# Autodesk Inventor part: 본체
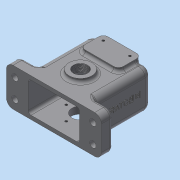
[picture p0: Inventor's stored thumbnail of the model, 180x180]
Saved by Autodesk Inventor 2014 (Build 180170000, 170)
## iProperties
Created: 2023-12
Part Number: 본체
Material: 일반
Document SubType Name: Modeling
Designer: dg
Density: 1 g/cm^3
Appearance: 기본값
Author: dg
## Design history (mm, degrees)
sketch "스케치1"
  geometry: L1 (50, -20)-(-50, -20); L2 (-50, -20)-(-50, 20); L3 (-50, 20)-(50, 20); L4 (50, 20)-(50, -20); L5 (31, -20)-(31, 20); L6 (-31, -20)-(-31, 20); 3 further points
  constraints: 12 end point, 4 point on line, 3 parallel, 2 midpoint, 2 perpendicular, 1 horizontal, 1 horizontal alignment, 1 vertical alignment
  dimensions: "d0" = 100 distance of L1.start L1.end; "d1" = 40 distance of L3.end L1.start; "d4" = 62 distance between parallel lines of L6 L5; "d5" = 31 distance from line of point (0, 0) L5
extrude "돌출1" new body sketch "스케치1" distance "d2" = 12; taper "d3" = 0 deg
extrude "돌출2" join sketch "스케치1" distance "d6" = 60; taper "d7" = 0 deg
sketch "스케치2"
  geometry: L1 (19, 72)-(81, 72) reference; L2 (30, 72)-(70, 72); L3 (70, 72)-(70, 48); L4 (70, 48)-(30, 48); L5 (30, 48)-(30, 72); L6 (100, 0)-(0, 0) reference; C1 r 12 at (50, 28); 2 further points
  constraints: 8 end point, 2 parallel, 2 vertical alignment, 1 centre point, 1 horizontal, 1 midpoint, 1 perpendicular, 1 point on line
  dimensions: "d8" = 24 distance between parallel lines of L4 L2; "d9" = 40 distance between parallel lines of L3 L5; "d12" = 24 diameter of C1; "d13" = 28 distance from line of C1.centre L6
extrude "돌출4" join sketch "스케치2" distance "d14" = 4; taper "d15" = 0 deg
sketch "스케치3"
  geometry: L1 (100, 0)-(0, 0) reference; C1 r 20 at (50, 28); 1 further point
  constraints: 1 centre point, 1 vertical alignment
  dimensions: "d16" = 40 diameter of C1; "d17" = 28 distance from line of L1 C1.centre
extrude "돌출5" join sketch "스케치3" distance "d18" = 4; taper "d19" = 0 deg
sketch "스케치5"
  geometry: L1 (-50, -20)-(50, -20) reference; L2 (50, 20)-(-50, 20) reference; L3 (-31, 20)-(-31, -20) reference; L4 (31, -20)-(31, 20) reference; L5 (-27, 16)-(27, 16); L6 (27, 16)-(27, -16); L7 (27, -16)-(-27, -16); L8 (-27, -16)-(-27, 16); 1 further point
  constraints: 8 end point, 2 parallel, 1 horizontal, 1 perpendicular
  dimensions: "d27" = 4 distance between parallel lines of L3 L8; "d28" = 4 distance between parallel lines of L4 L6; "d29" = 4 distance between parallel lines of L2 L5; "d30" = 4 distance between parallel lines of L1 L7
extrude "돌출7" cut sketch "스케치5" distance "d31" = 68; taper "d32" = 0 deg
sketch "스케치6"
  geometry: L1 (-20, 44)-(-20, 20) reference; L2 (-20, 20)-(20, 20) reference; L3 (20, 20)-(20, 44) reference; L4 (20, 44)-(-20, 44) reference; C1 r 12 at (0, 0) reference; 2 further points
  constraints: 1 coincident
hole "구멍1" sketch "스케치6" at (0, 0) diameter "d33" = 14.917; stored, may be unused: countersink angle "d37" = 90 deg, drill point angle "d39" = 0 deg; dims "d34" = 6, "d35" = 4, "d36" = 2, "d38" = 8
sketch "스케치7"
  geometry: C1 r 20 at (0, 0) reference; A1 r 15 centre (0, 0) between (0, 15) and (0, -15); 3 further points
  constraints: 4 point on circle, 2 horizontal alignment, 2 vertical alignment, 1 centre point, 1 coincident
  dimensions: "d40" = 30 diameter of A1
hole "구멍2" sketch "스케치7" at (0, 15), (0, -15), (-15, 0), (15, 0) diameter "d41" = 2.459; stored, may be unused: countersink angle "d45" = 90 deg, drill point angle "d47" = 0 deg; dims "d42" = 6, "d43" = 4, "d44" = 2, "d46" = 8
sketch "스케치8"
  geometry: C1 r 20 at (0, 0) reference; 2 further points
  constraints: 1 coincident
hole "구멍3" sketch "스케치8" at (0, 0) diameter "d48" = 18; stored, may be unused: countersink angle "d52" = 90 deg, drill point angle "d54" = 0 deg; dims "d49" = 6, "d50" = 4, "d51" = 2, "d53" = 8
sketch "스케치11"
  geometry: L1 (0, -12)-(-40, -12) reference; L2 (-44, 28)-(-44, 4) reference; 2 further points
  constraints: 1 other
  dimensions: "d82" = 40 distance from line of L1 point (-21, 28); "d83" = 23 distance from line of L2 point (-21, 28)
feature "엠보싱1" sketch "스케치11" dims "d8" = 24, "d9" = 40, "d84" = 0.5, "d85" = 0
sketch "스케치12"
  geometry: L1 (-31, -20)-(-31, 20) reference; L2 (-50, 20)-(-31, 20) reference; L3 (-50, -20)-(-50, 20) reference; L4 (-31, -20)-(-50, -20) reference; 5 further points
  constraints: 2 horizontal alignment, 2 vertical alignment
  dimensions: "d86" = 82 distance of point (41, 10) point (-41, 10); "d87" = 20 distance of point (-41, -10) point (-41, 10); "d88" = 10 distance from line of L4 point (-41, -10); "d89" = 41 horizontal distance of point (0, 0) point (-41, 10)
hole "구멍7" sketch "스케치12" at (-41, 10), (41, 10), (41, -10), (-41, -10) diameter "d90" = 6.6; stored, may be unused: countersink angle "d94" = 90 deg, drill point angle "d96" = 0 deg; dims "d91" = 6, "d92" = 11, "d93" = 6.6, "d95" = 8
chamfer "모따기1" distance "d97" = 1; stored, may be unused: second distance "d98" = 2, angle "d99" = 45 deg
fillet "모깎기1" dims "d100" = 7
fillet "모깎기4" dims "d103" = 7
fillet "모깎기5" dims "d104" = 7
extrude "돌출8" join sketch "스케치2" distance "d105" = 4; taper "d107" = 0 deg; dims "d106" = 10, "d108" = 0
sketch "스케치13"
  geometry: L1 (0, 0)-(40, 0) reference; L2 (0, 0)-(0, -6) reference; L3 (0, -6)-(40, -6); L4 (40, -6)-(40, 0); L5 (40, 0)-(0, 0); L6 (0, 0)-(0, -6); 1 further point
  constraints: 8 end point, 2 parallel, 1 horizontal, 1 perpendicular
extrude "돌출9" cut sketch "스케치13" distance "d109" = 20; taper "d110" = 0 deg
fillet "모깎기6" dims "d111" = 5
node "작업 평면1"
sketch "스케치14"
  geometry: L1 (15, -24)-(-15, -24) reference; L2 (-17.321, 17)-(17.321, 17); L3 (-17.321, -3)-(17.321, -3); A1 r 20 centre (0, 7) between (-17.321, 17) and (-17.321, -3); A2 r 20 centre (0, 7) between (17.321, -3) and (17.321, 17); 1 further point
  constraints: 4 end point, 4 point on circle, 3 parallel, 2 centre point, 1 vertical alignment
  dimensions: "d115" = 31 distance from line of L1 A1.centre; "d116" = 20 distance between parallel lines of L3 L2; "d117" = 20 radius of A2; "d118" = 20 radius of A1
extrude "돌출10" join sketch "스케치14" stored distance "d119" = 20; taper "d120" = 0 deg
sketch "스케치15"
  geometry: L1 (65, 72)-(35, 72) reference; 3 further points
  constraints: 1 horizontal alignment
  dimensions: "d121" = 28 distance of point (64, 66) point (36, 66); "d122" = 14 horizontal distance of point (50, 12) point (36, 66); "d123" = 6 distance from line of L1 point (36, 66)
hole "구멍8" sketch "스케치15" at (36, 66), (64, 66) diameter "d124" = 2.459; stored, may be unused: countersink angle "d128" = 90 deg, drill point angle "d130" = 0 deg; dims "d125" = 6, "d126" = 11, "d127" = 6.6, "d129" = 8
sketch "스케치16"
  geometry: L1 (15, -24)-(-15, -24) reference; A1 r 20 centre (0, 7) between (-17.321, 17) and (-17.321, -3) reference; 2 further points
  constraints: 1 coincident
  dimensions: "d131" = 31 distance from line of L1 point (0, 7)
hole "구멍9" sketch "스케치16" at (0, 7) diameter "d132" = 16; stored, may be unused: countersink angle "d136" = 90 deg, drill point angle "d138" = 0 deg; dims "d133" = 6, "d134" = 11, "d135" = 6.6, "d137" = 8
sketch "스케치17"
  geometry: C1 r 8 at (0, 7) reference; 3 further points
  constraints: 2 horizontal alignment
  dimensions: "d139" = 28 distance of point (14, 7) point (-14, 7); "d140" = 14 distance of C1.centre point (-14, 7)
hole "구멍10" sketch "스케치17" at (-14, 7), (14, 7) diameter "d141" = 2.459; stored, may be unused: countersink angle "d145" = 90 deg, drill point angle "d147" = 0 deg; dims "d142" = 6, "d143" = 11, "d144" = 6.6, "d146" = 8
fillet "모깎기8" dims "d148" = 3
fillet "모깎기9" dims "d149" = 3
fillet "모깎기10" dims "d150" = 3
fillet "모깎기11" dims "d151" = 3
fillet "모깎기12" dims "d152" = 3
fillet "모깎기13" dims "d153" = 3
fillet "모깎기14" dims "d154" = 3
chamfer "모따기2" distance "d155" = 1; stored, may be unused: second distance "d156" = 2, angle "d157" = 45 deg
fillet "모깎기15" dims "d158" = 3
node "솔리드1"
node "투영된 루프2"
other parameters: "d113" = 4
